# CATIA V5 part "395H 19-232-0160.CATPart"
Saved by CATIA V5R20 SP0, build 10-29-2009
Part number: 395H 19-232-0160
Source: Unknown
Bounding box of the stored display mesh (mm): x -46.007 to 46.007, y -45.972 to 45.972, z -100 to 20
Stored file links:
  C:\Users\Utente\Desktop\3D files 395H FCA\395H 19-232-0160.CATPart
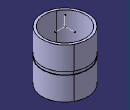
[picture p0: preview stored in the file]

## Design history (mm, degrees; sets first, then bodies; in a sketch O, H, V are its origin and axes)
Set1
  Line1 to Line3: stored without definition
  Point1 "Punto.4": stored without definition
Body1 (main body)
  Solid1 "PartBody": solid without history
